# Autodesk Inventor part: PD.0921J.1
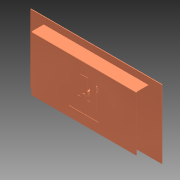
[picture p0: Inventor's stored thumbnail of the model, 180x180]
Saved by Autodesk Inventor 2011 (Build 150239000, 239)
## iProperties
Created: 2014-06
Part Number: PD.0921J.1
Document SubType Name: Modeling
Designer: Evgeny
Density: 1 g/cm^3
Author: Evgeny
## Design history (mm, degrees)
sketch "Эскиз1"
  geometry: L1 (-81, 42.5)-(81, 42.5); L2 (81, 42.5)-(81, -42.5); L3 (81, -42.5)-(-81, -42.5); L4 (-81, -42.5)-(-81, 42.5); L5 (23, 27.5)-(23, -27.5); L6 (23, -27.5)-(-23, -27.5); L7 (-23, -27.5)-(-23, 27.5); L8 (19, 27.5)-(19, -23.5); L9 (19, -23.5)-(-19, -23.5); L10 (-19, -23.5)-(-19, 27.5); L11 (-23, 27.5)-(-19, 27.5); L12 (19, 27.5)-(23, 27.5); L13 (-9.5, 27.5)-(9.5, 27.5); L14 (9.5, 27.5)-(9.5, -6.5); L15 (-9.5, -6.5)-(-9.5, 27.5); L16 (-5.5, -6.5)-(-5.5, 23.5); L17 (-5.5, 23.5)-(5.5, 23.5); L18 (5.5, 23.5)-(5.5, -6.5); L19 (9.5, -6.5)-(5.5, -6.5); L20 (-5.5, -6.5)-(-9.5, -6.5); C1 r 3.4 at (0, -3); 1 further point
  constraints: 40 end point, 10 parallel, 4 horizontal, 4 perpendicular, 3 collinear, 1 centre point
  dimensions: "d0" = 85 distance between parallel lines of L3 L1; "d1" = 162 distance between parallel lines of L2 L4; "d2" = 81 distance from line of L4 point (0, 0); "d3" = 42.5 distance from line of L3 point (0, 0); "d4" = 4 distance between parallel lines of L10 L7; "d5" = 4 distance between parallel lines of L5 L8; "d6" = 4 distance between parallel lines of L6 L9; "d7" = 55 distance between parallel lines of L12 L6; "d8" = 27.5 distance from line of point (0, 0) L6; "d9" = 46 distance between parallel lines of L5 L7; "d10" = 23 distance from line of L7 point (0, 0); "d11" = 4 distance between parallel lines of L16 L15; "d12" = 4 distance between parallel lines of L18 L14; "d13" = 4 distance between parallel lines of L13 L17; "d15" = 19 distance between parallel lines of L14 L15; "d16" = 9.5 distance from line of point (0, 0) L15; "d19" = 6.8 diameter of C1; "d20" = 45.5 distance from line of L1 C1.centre; "d43" = 49 distance between parallel lines of L1 L20
extrude "Выдавливание2" new body sketch "Эскиз1" distance "d21" = 0.5; taper "d22" = 0 deg
extrude "Выдавливание3" join sketch "Эскиз1" distance "d23" = 1.5; taper "d25" = 0 deg; dims "d24" = 19.5, "d26" = 0
sketch "Эскиз2"
  geometry: L1 (81, -42.5)-(81, 42.5) reference; L2 (-81, 42.5)-(81, 42.5); L3 (81, 42.5)-(81, 42); L4 (81, 42)-(-81, 42); L5 (-81, 42)-(-81, 42.5); 1 further point
  constraints: 8 end point, 2 parallel, 1 horizontal, 1 perpendicular, 1 point on line
  dimensions: "d27" = 0.5 distance between parallel lines of L4 L2
extrude "Выдавливание4" join sketch "Эскиз2" distance "d28" = 18.5; taper "d29" = 0 deg
fillet "Сопряжение1" dims "d30" = 1.5
fillet "Сопряжение2" dims "d31" = 1
sketch "Эскиз3"
  geometry: L1 (-81, 42.5)-(81, 42.5) reference; L2 (-101.5, 53)-(101.5, 53); L3 (101.5, 53)-(101.5, -53); L4 (101.5, -53)-(-101.5, -53); L5 (-101.5, -53)-(-101.5, 53); C1 r 4.5 at (0, -3); 2 further points
  constraints: 8 end point, 2 parallel, 1 centre point, 1 horizontal, 1 perpendicular
  dimensions: "d32" = 9 diameter of C1; "d33" = 56 distance from line of L2 C1.centre; "d34" = 106 distance between parallel lines of L4 L2; "d35" = 203 distance between parallel lines of L3 L5; "d36" = 101.5 distance from line of L5 C1.centre; "d37" = 20.5 distance from line of L5 point (-81, 42); "d38" = 10.5 distance between parallel lines of L2 L1
extrude "Выдавливание6" join sketch "Эскиз3" distance "d41" = 1; taper "d42" = 0 deg
node "Твердое тело2"
